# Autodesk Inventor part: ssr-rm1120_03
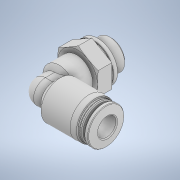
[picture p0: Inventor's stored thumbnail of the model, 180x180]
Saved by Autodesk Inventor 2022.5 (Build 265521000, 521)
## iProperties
Created: 2022-03
Part Number: ssr-rm1120_03
Material: 一般
Document SubType Name: Modeling
Designer: ImaoCorp
Density: 1 g/cm^3
Appearance: 既定
Author: ImaoCorp
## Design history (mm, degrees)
feature "ssr-rm1120_03"
node "ソリッド1"
